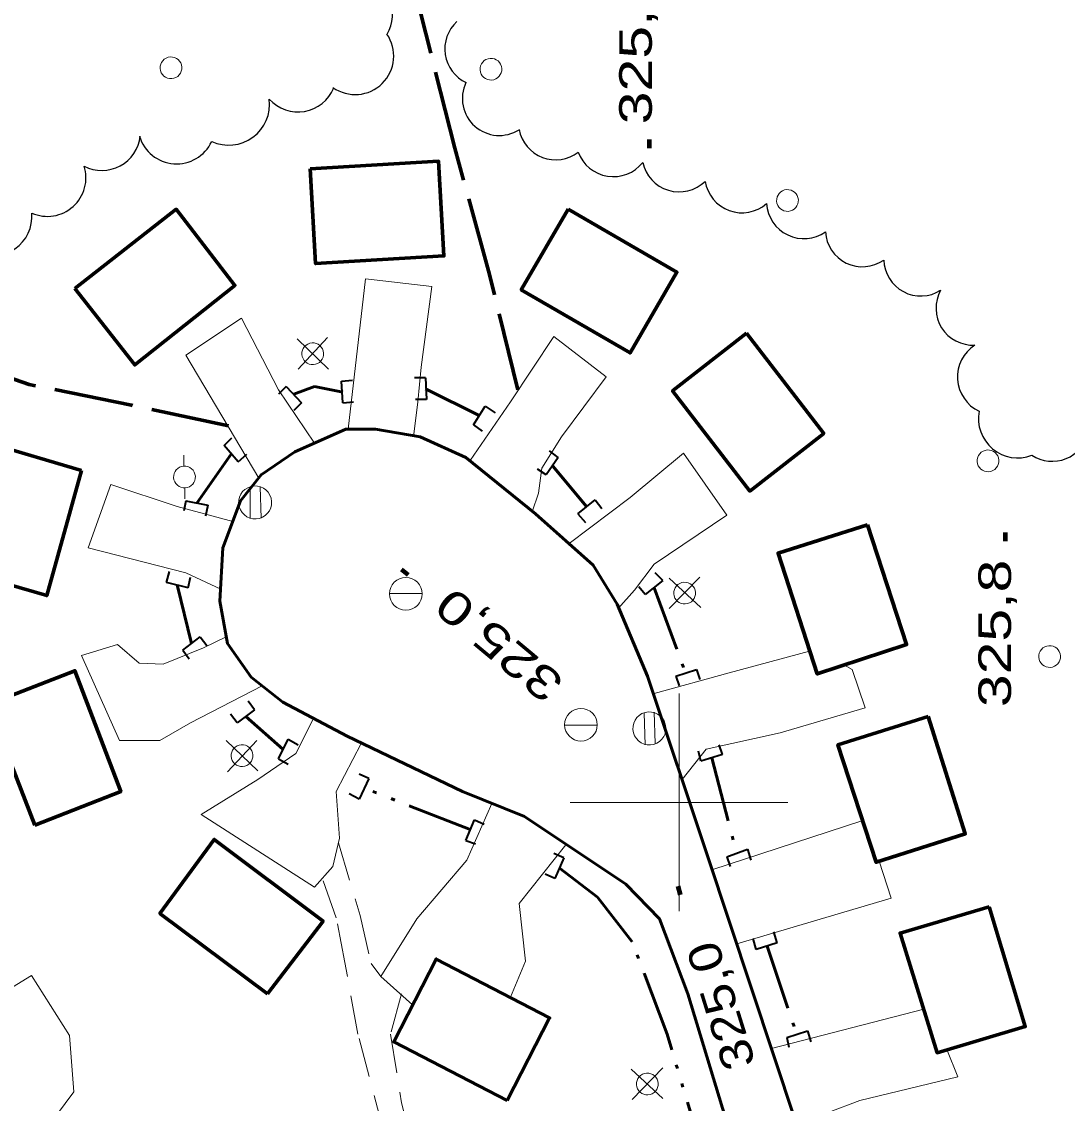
# Model space of a CAD drawing. Extents: x 240591 to 242335, y 5323482 to 5326937.
# Drawn here: x 241139.6 to 241235.7, y 5325172.3 to 5325271.7 of the extents above; entities that cross this region are included whole.
import ezdxf
from ezdxf.enums import TextEntityAlignment as Align

# ---------------------------------------------------------------- set-up
doc = ezdxf.new("R2010")
doc.units = 0
doc.header["$LTSCALE"] = 1.2
for name, pattern in [('DASH_DOUBLE_DOT', [9.2, 5, -1.2, 0.3, -1.2, 0.3, -1.2]), ('LONG_DASHED', [7.5, 6, -1.5]), ('MEDIUM_DASHED', [4.5, 3, -1.5])]:
    doc.linetypes.add(name, pattern=pattern)
for name, color, linetype, lineweight in [('19', 7, 'Continuous', 13), ('21', 7, 'Continuous', 53), ('22', 7, 'LONG_DASHED', 70), ('26', 7, 'Continuous', 35), ('3', 7, 'Continuous', 140), ('31', 7, 'Continuous', 70), ('36', 7, 'Continuous', 13), ('4', 7, 'DASH_DOUBLE_DOT', 53), ('44', 7, 'Continuous', 25), ('61', 7, 'Continuous', 13)]:
    doc.layers.add(name, color=color, linetype=linetype, lineweight=lineweight)

msp = doc.modelspace()

# ---------------------------------------------------------------- linework, layer by layer
at = {"layer": '19'}
msp.add_line((241208.5, 5325177.4), (241222.5, 5325181), dxfattribs=at)
for points in [[(241169.6, 5325234.3), (241171.2, 5325248.1), (241177.3, 5325247.4), (241176.3, 5325240), (241176, 5325236.8), (241175.6, 5325233.6)], [(241161.4, 5325229.8), (241154.7, 5325241.1), (241159.8, 5325244.5), (241163.2, 5325237.9), (241166.5, 5325233)], [(241180.8, 5325231.4), (241184.5, 5325236.8), (241188.5, 5325242.8), (241193.3, 5325239.1), (241189.2, 5325233.6), (241187.4, 5325230.7), (241187.1, 5325228.4), (241186.5, 5325226.7)], [(241189.9, 5325223.8), (241195.5, 5325228), (241200.4, 5325232.1), (241204.4, 5325226.4), (241197.7, 5325221.9), (241195.9, 5325219.5), (241194.4, 5325217.8)], [(241157.9, 5325219.6), (241154.7, 5325221.1), (241145.7, 5325223.4), (241147.8, 5325229.2), (241153.9, 5325227.2), (241156.4, 5325226.5), (241159, 5325225.8)], [(241161.7, 5325210.7), (241155.1, 5325207.3), (241152.3, 5325205.7), (241148.6, 5325205.7), (241145.1, 5325213.5), (241148.4, 5325214.5), (241150.4, 5325212.8), (241152.6, 5325212.7), (241156.3, 5325214.2), (241158.4, 5325215.2)], [(241197.7, 5325210), (241204.6, 5325211.9), (241212, 5325213.9)], [(241215.2, 5325212.6), (241215.9, 5325212.2), (241217.1, 5325208.7), (241209.3, 5325206.4), (241202.5, 5325204.9), (241200.3, 5325202.1)], [(241170.8, 5325205.4), (241168.5, 5325201), (241168.8, 5325196.7), (241168.2, 5325194.1), (241166.5, 5325192.2), (241156.1, 5325198.9), (241161.3, 5325202.1), (241164.8, 5325204.5), (241166.4, 5325207.7)], [(241175.5, 5325181.4), (241172.6, 5325184), (241175.9, 5325189.3), (241180.5, 5325194.7), (241182.8, 5325199.9)], [(241203, 5325193.8), (241210.6, 5325196.3), (241216.8, 5325198.3)], [(241189.6, 5325196.1), (241185.3, 5325190.7), (241185.9, 5325185.4), (241184.5, 5325182.1)], [(241218.4, 5325194.6), (241219.5, 5325191.2), (241205.3, 5325187)], [(241104.2, 5325160.9), (241119.6, 5325172), (241117.4, 5325174.8), (241121.4, 5325178.5), (241124.6, 5325174.4), (241131, 5325176.8), (241136.6, 5325181.7), (241140.5, 5325184.1), (241144, 5325178.6), (241144.4, 5325173.4), (241142, 5325170.2), (241135, 5325165.5), (241132.4, 5325168.6), (241122.8, 5325163), (241113.4, 5325158.1), (241108.3, 5325155.6)], [(241224.6, 5325177.3), (241225.6, 5325174.8), (241216.6, 5325172.6), (241210.8, 5325170.4)]]:
    msp.add_lwpolyline(points, dxfattribs=at)
at = {"layer": '19', "linetype": 'MEDIUM_DASHED'}
for points in [[(241168.7, 5325196.3), (241170.7, 5325189.6), (241171.7, 5325185.2), (241172.6, 5325184)], [(241167.5, 5325100.9), (241170.3, 5325106.2), (241173.5, 5325115.5), (241174.9, 5325126.6), (241175.3, 5325136.5), (241174.9, 5325146.8), (241174.8, 5325148.4), (241174.4, 5325160.3), (241172.9, 5325169.6), (241170.5, 5325178.7), (241169.3, 5325185.3), (241168.5, 5325189.4), (241167.2, 5325193.1)], [(241174.5, 5325182.4), (241173.5, 5325178.7), (241174.5, 5325172.4), (241176.5, 5325164.9), (241177.4, 5325152.3), (241177.5, 5325141.4), (241178.1, 5325132.1), (241177.6, 5325121.6), (241175.5, 5325112.4), (241172.6, 5325104), (241170, 5325099.1), (241167.5, 5325097.7)]]:
    msp.add_lwpolyline(points, dxfattribs=at)
at = {"layer": '21'}
for points in [[(241180.1, 5325201), (241169.5, 5325206.1), (241163.6, 5325209.2), (241160.7, 5325211.5), (241158.5, 5325214.6), (241157.8, 5325218.5), (241158.1, 5325223.4), (241159.7, 5325227.7), (241161.6, 5325230.1), (241164.7, 5325232.2), (241169.4, 5325234.3), (241172.1, 5325234.3), (241176.2, 5325233.6), (241180.4, 5325231.7), (241186.8, 5325226.5), (241192.1, 5325221.8), (241194.3, 5325218.2), (241197.1, 5325211.6), (241202.6, 5325195.1), (241210.7, 5325170.7), (241217.1, 5325150.2), (241223.8, 5325128.8), (241230.3, 5325108), (241238.1, 5325083.1)], [(241235, 5325072.5), (241234.3, 5325075.2), (241223.8, 5325108.3), (241214.4, 5325138.7), (241204, 5325171.9), (241200.8, 5325182.4), (241198.2, 5325189.3), (241195.1, 5325192.5), (241185.8, 5325198.7), (241180.1, 5325201)]]:
    msp.add_lwpolyline(points, dxfattribs=at)
at = {"layer": '22'}
for points in [[(241185.2, 5325237.9), (241182.6, 5325248.5), (241179.4, 5325260.1), (241175.6, 5325275.1), (241172.4, 5325284.8), (241171.2, 5325290.3), (241171, 5325294.3), (241169.8, 5325300.3), (241168.7, 5325307.3)], [(241158.6, 5325234.6), (241149.7, 5325236.5), (241140.3, 5325238.4), (241130.8, 5325241.7), (241125.3, 5325245.9), (241119.9, 5325254), (241115.2, 5325261.3), (241110.8, 5325267.3), (241110.3, 5325270.3)]]:
    msp.add_lwpolyline(points, dxfattribs=at)
at = {"layer": '26'}
for p, q in [((241169, 5325238.7), (241170, 5325238.8)), ((241169.1, 5325236.7), (241169, 5325238.7)), ((241176.7, 5325239), (241175.7, 5325239)), ((241176.7, 5325239), (241176.8, 5325237)), ((241163.9, 5325238.2), (241163.2, 5325237.5)), ((241163.9, 5325238.2), (241165.3, 5325236.7)), ((241165.3, 5325236.7), (241164.6, 5325236)), ((241169.1, 5325236.7), (241170.1, 5325236.8)), ((241176.8, 5325237), (241175.8, 5325237)), ((241181.1, 5325234.7), (241182.2, 5325236.4)), ((241182.2, 5325236.4), (241183.1, 5325235.8)), ((241181.1, 5325234.7), (241181.9, 5325234.1)), ((241158.2, 5325232.8), (241158.9, 5325233.5)), ((241159.5, 5325231.3), (241158.2, 5325232.8)), ((241159.5, 5325231.3), (241160.3, 5325232)), ((241188.9, 5325231.7), (241187.8, 5325230.1)), ((241188.9, 5325231.7), (241188.1, 5325232.3)), ((241187.8, 5325230.1), (241187, 5325230.6)), ((241154.7, 5325227.7), (241154.5, 5325226.8)), ((241154.7, 5325227.7), (241156.7, 5325227.3)), ((241190.7, 5325226.5), (241192.3, 5325227.8)), ((241192.3, 5325227.8), (241192.9, 5325227)), ((241156.7, 5325227.3), (241156.5, 5325226.3)), ((241190.7, 5325226.5), (241191.4, 5325225.7)), ((241152.9, 5325220.2), (241153.2, 5325221.2)), ((241154.9, 5325219.7), (241155.1, 5325220.7)), ((241198.5, 5325220.4), (241197.8, 5325221.1)), ((241154.9, 5325219.7), (241152.9, 5325220.2)), ((241196.9, 5325219.1), (241196.3, 5325219.8)), ((241198.5, 5325220.4), (241196.9, 5325219.1)), ((241154.4, 5325214), (241156, 5325215.2)), ((241156, 5325215.2), (241156.6, 5325214.4)), ((241154.4, 5325214), (241155, 5325213.2)), ((241199.7, 5325211.6), (241201.6, 5325212.2)), ((241201.6, 5325212.2), (241201.9, 5325211.3)), ((241199.7, 5325211.6), (241200, 5325210.7)), ((241161, 5325208.5), (241160.4, 5325209.3)), ((241159.4, 5325207.3), (241158.8, 5325208.1)), ((241161, 5325208.5), (241159.4, 5325207.3)), ((241163.2, 5325204), (241164.1, 5325205.8)), ((241164.1, 5325205.8), (241165, 5325205.3)), ((241204, 5325204.4), (241203.7, 5325205.3)), ((241163.2, 5325204), (241164.1, 5325203.5)), ((241202, 5325203.8), (241201.8, 5325204.7)), ((241204, 5325204.4), (241202, 5325203.8)), ((241171.5, 5325202.2), (241170.6, 5325202.6)), ((241171.5, 5325202.2), (241170.6, 5325200.3)), ((241170.6, 5325200.3), (241169.7, 5325200.8)), ((241180.4, 5325196.5), (241181.2, 5325198.4)), ((241181.2, 5325198.4), (241182.1, 5325198)), ((241180.4, 5325196.5), (241181.3, 5325196.2)), ((241189.4, 5325194.9), (241188.5, 5325195.3)), ((241189.4, 5325194.9), (241188.6, 5325193)), ((241204.4, 5325195), (241206.3, 5325195.7)), ((241204.4, 5325195), (241204.7, 5325194.1)), ((241206.3, 5325195.7), (241206.6, 5325194.7)), ((241188.6, 5325193), (241187.7, 5325193.4)), ((241209, 5325187.1), (241208.7, 5325188.1)), ((241207.1, 5325186.5), (241206.8, 5325187.5)), ((241209, 5325187.1), (241207.1, 5325186.5)), ((241209.9, 5325178.4), (241211.8, 5325179)), ((241211.8, 5325179), (241212.1, 5325178)), ((241209.9, 5325178.4), (241210.1, 5325177.5))]:
    msp.add_line(p, q, dxfattribs=at)
at = {"layer": '3'}
for p, q in [((241197.3, 5325260.1), (241197.3, 5325260.9)), ((241230, 5325224), (241230, 5325224.8)), ((241174.5, 5325221.4), (241175.1, 5325220.9)), ((241199.9, 5325192.3), (241200.1, 5325191.5))]:
    msp.add_line(p, q, dxfattribs=at)
at = {"layer": '31'}
for points in [[(241166.1, 5325258.2), (241177.9, 5325258.9), (241178.4, 5325250.2), (241166.6, 5325249.5)], [(241144.5, 5325247.2), (241153.8, 5325254.5), (241159.2, 5325247.5), (241150, 5325240.2)], [(241189.8, 5325254.5), (241199.8, 5325248.7), (241195.5, 5325241.3), (241185.5, 5325247.1)], [(241206.2, 5325243.1), (241213.3, 5325233.9), (241206.5, 5325228.6), (241199.4, 5325237.8)], [(241145.1, 5325230.5), (241141.9, 5325219), (241133.3, 5325221.5), (241136.6, 5325233)], [(241217.3, 5325225.5), (241220.9, 5325214.5), (241212.7, 5325211.8), (241209.1, 5325222.9)], [(241140.8, 5325197.9), (241136.5, 5325209), (241144.5, 5325212.1), (241148.7, 5325201)], [(241222.9, 5325207.9), (241226.3, 5325197.1), (241218.1, 5325194.5), (241214.6, 5325205.3)], [(241162.2, 5325182.4), (241152.3, 5325189.8), (241157.3, 5325196.6), (241167.3, 5325189.1)], [(241228.5, 5325190.4), (241231.8, 5325179.4), (241223.7, 5325177), (241220.3, 5325188)], [(241184.2, 5325172.6), (241173.8, 5325178), (241177.7, 5325185.6), (241188.1, 5325180.2)]]:
    msp.add_lwpolyline(points, close=True, dxfattribs=at)
at = {"layer": '36'}
for p, q in [((241167.8, 5325239.8), (241164.9, 5325242.6)), ((241165, 5325239.8), (241167.7, 5325242.7)), ((241154.5, 5325231.9), (241154.5, 5325230.9)), ((241154.6, 5325227.9), (241154.6, 5325228.9)), ((241160.6, 5325229), (241160.6, 5325226.1)), ((241161.6, 5325226.1), (241161.5, 5325229)), ((241199.1, 5325217.8), (241201.9, 5325220.7)), ((241202, 5325217.9), (241199.1, 5325220.6)), ((241173.4, 5325219.2), (241176.4, 5325219.2)), ((241196.8, 5325208.2), (241196.9, 5325205.3)), ((241197.8, 5325205.4), (241197.7, 5325208.3)), ((241189.5, 5325207.1), (241192.5, 5325207.1)), ((241161.3, 5325202.9), (241158.4, 5325205.7)), ((241158.5, 5325202.8), (241161.2, 5325205.7)), ((241198.5, 5325172.8), (241195.6, 5325175.5)), ((241195.7, 5325172.7), (241198.5, 5325175.6))]:
    msp.add_line(p, q, dxfattribs=at)
for centre in [(241174.899, 5325219.162), (241190.989, 5325207.132)]:
    msp.add_circle(centre, 1.5, dxfattribs=at)
for centre, major_axis in [((241153.323, 5325267.49), (0.261, -0.965)), ((241182.713, 5325267.36), (0.261, -0.965)), ((241209.963, 5325255.3), (0.261, -0.965)), ((241166.344, 5325241.217), (-0.261, 0.965)), ((241228.383, 5325231.38), (0.261, -0.965)), ((241154.561, 5325229.899), (-0.261, 0.965)), ((241161.054, 5325227.557), (-0.396, 1.465)), ((241200.514, 5325219.227), (-0.261, 0.965)), ((241234.043, 5325213.4), (0.261, -0.965)), ((241197.274, 5325206.797), (-0.396, 1.465)), ((241159.844, 5325204.297), (-0.261, 0.965)), ((241197.084, 5325174.127), (-0.261, 0.965))]:
    msp.add_ellipse(centre, major_axis=major_axis, ratio=0.99964, dxfattribs=at)
at = {"layer": '4'}
for p, q in [((241176.7, 5325238), (241181.7, 5325235.5)), ((241155.7, 5325227.5), (241158.9, 5325232.1)), ((241188.4, 5325230.9), (241191.5, 5325227.2)), ((241155.2, 5325214.6), (241153.9, 5325220)), ((241197.7, 5325219.7), (241200.6, 5325211.9)), ((241163.6, 5325204.9), (241160.2, 5325207.9)), ((241203, 5325204.1), (241205.3, 5325195.3)), ((241180.8, 5325197.5), (241171.1, 5325201.3)), ((241208.1, 5325186.8), (241210.8, 5325178.7))]:
    msp.add_line(p, q, dxfattribs=at)
for points in [[(241164.6, 5325237.5), (241166.5, 5325238.2), (241169.1, 5325237.7)], [(241202.5, 5325166.7), (241198.9, 5325178.7), (241195.7, 5325187.2), (241192.5, 5325191.3), (241189, 5325194)]]:
    msp.add_lwpolyline(points, dxfattribs=at)
at = {"layer": '44'}
for centre, major_axis, ratio, start_param, end_param in [((241170.137, 5325272.424), (2.637, 2.383), 0.998823, 5.003539, 6.885905), ((241181.889, 5325269.211), (0.154, -3.407), 0.999855, 3.836193, 5.796502), ((241170.237, 5325268.579), (2.78, 2.207), 0.999871, 3.429152, 6.215727), ((241164.986, 5325266.991), (0.095, -3.553), 0.998875, 5.419706, 7.438469), ((241183.488, 5325264.666), (3.338, 0.624), 0.999252, 2.510619, 5.094704), ((241158.624, 5325264.136), (2.227, -3.025), 0.999981, 5.2192, 7.345893), ((241188.656, 5325262.438), (2.948, 1.707), 0.998454, 2.801923, 4.846742), ((241146.975, 5325261.601), (3.141, 1.644), 0.999943, 3.75173, 5.689495), ((241153.838, 5325262.212), (0.057, -3.554), 0.99869, 4.980951, 7.404715), ((241193.964, 5325260.92), (-0.544, -3.39), 0.998579, 5.219051, 7.347292), ((241141.962, 5325257.388), (2.798, 2.185), 0.999871, 3.634188, 5.92696), ((241200.02, 5325259.533), (-1.219, -3.218), 0.99913, 5.288701, 7.409665), ((241205.783, 5325257.598), (-1.322, -3.166), 0.998482, 5.267862, 7.39427), ((241211.46, 5325255.232), (-1.482, -3.101), 0.999994, 5.222939, 7.346645), ((241136.975, 5325253.814), (1.525, 3.228), 0.999995, 3.113591, 5.245374), ((241216.852, 5325252.618), (3.396, 0.276), 0.999995, 3.115522, 5.243547), ((241222.215, 5325249.929), (3.4, 0.211), 0.999555, 3.108723, 5.213849), ((241227.01, 5325245.41), (-1.439, -3.086), 0.999111, 4.645052, 6.769839), ((241229.063, 5325239.083), (-3.473, -0.224), 0.999978, 5.219716, 7.346306), ((241231.115, 5325235.26), (3.561, -0.592), 0.999995, 3.116693, 5.243945), ((241234.275, 5325234.739), (3.368, 0.503), 0.999893, 3.98458, 5.912095)]:
    msp.add_ellipse(centre, major_axis=major_axis, ratio=ratio, start_param=start_param, end_param=end_param, dxfattribs=at)
at = {"layer": '61'}
for points in [[(241200, 5325210), (241200, 5325200), (241200, 5325190)], [(241190, 5325200), (241200, 5325200), (241210, 5325200)]]:
    msp.add_lwpolyline(points, dxfattribs=at)

# ---------------------------------------------------------------- texts
at = {"layer": '3', "width": 1.35}
msp.add_text('325,4', height=3, rotation=90, dxfattribs=at).set_placement((241197.5, 5325262.3))
at = {"layer": '3'}
for s, rotation, width, p in [('325,8', 90, 1.35, (241230.5, 5325222.3)), ('325,0', 140.097, 1.35, (241179.224, 5325219.927)), ('325,0', 107.351, 1.2, (241203.474, 5325187.505))]:
    msp.add_text(s, height=3, rotation=rotation, dxfattribs=dict(at, width=width)).set_placement(p, align=Align.RIGHT)

doc.saveas('drawing.dxf')
